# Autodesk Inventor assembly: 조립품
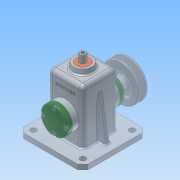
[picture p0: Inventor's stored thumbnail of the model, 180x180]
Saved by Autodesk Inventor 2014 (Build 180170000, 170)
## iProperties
Created: 2016-02
Part Number: 조립품
Document SubType Name: Assembly
Designer: net
Author: net
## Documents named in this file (15)
- C:\Users\net\Desktop\460211V1018\조립품.iam
- C:\Users\net\Desktop\460211V1018\본체.ipt
- C:\Users\net\Desktop\460211V1018\뒤커버.ipt
- C:\Users\net\Desktop\460211V1018\베어링 12 x 32 x 10.ipt
- C:\Users\net\Desktop\460211V1018\볼트 M4 x 12.ipt
- C:\Users\net\Desktop\460211V1018\앞커버.ipt
- C:\Users\net\Desktop\460211V1018\오일실 12 25 7.ipt
- C:\Users\net\Desktop\460211V1018\편심축.ipt
- C:\Users\net\Desktop\460211V1018\키 4 x 4 x 10.ipt
- C:\Users\net\Desktop\460211V1018\V벨트풀리.ipt
- C:\Users\net\Desktop\460211V1018\링크.ipt
- C:\Users\net\Desktop\460211V1018\슬라이드.ipt
- C:\Users\net\Desktop\460211V1018\핀 5 x 18.ipt
- C:\Users\net\Desktop\460211V1018\멈춤나사 M3x8.ipt
- C:\Users\net\Desktop\460211V1018\부시.ipt
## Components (10 placed, 3 different names)
1. ISO 4762 M4 x 12:1
2. ISO 4762 M4 x 12:2
3. ISO 4762 M4 x 12:3
4. ISO 4762 M4 x 12:4
5. ISO 4762 M4 x 12:5
6. ISO 4762 M4 x 12:6
7. ISO 4762 M4 x 12:7
8. ISO 4762 M4 x 12:8
9. V벨트풀리:1 — 각도:2
10. 핀 5 x 18:1
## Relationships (1: Angle 1)
- 각도:2 [Angle]: V벨트풀리:1
